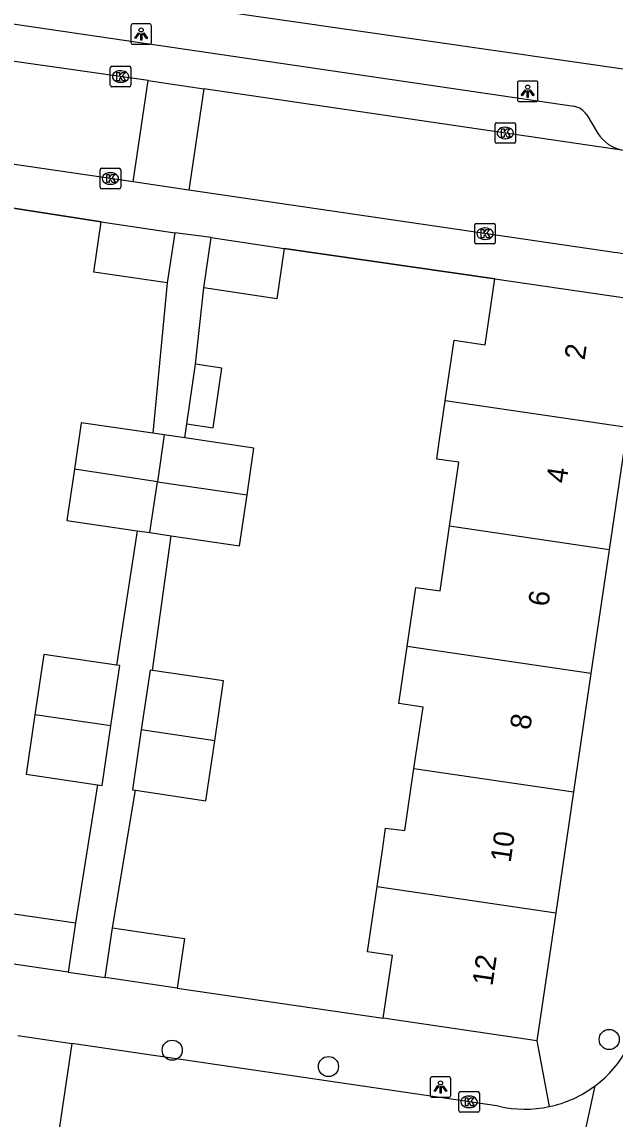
# Model space of a CAD drawing. Extents: x 163686 to 164493, y 382719 to 383870.
# Drawn here: x 163953.6 to 163982.4, y 383035.1 to 383088.5 of the extents above; entities that cross this region are included whole.
import ezdxf

# ---------------------------------------------------------------- set-up
doc = ezdxf.new("R2010")
doc.units = 0
for name, color, linetype in [('IMGEO_Boom', 7, 'Continuous'), ('IMGEO_Kolk', 7, 'Continuous'), ('IMGEO_Lichtpunt', 7, 'Continuous'), ('IMGEO_Muur', 7, 'Continuous'), ('IMGEO_Pand', 7, 'Continuous'), ('IMGEO_Pand_nummerreeks', 7, 'Continuous'), ('IMGEO_Rijbaan_lokaal_open', 7, 'Continuous'), ('IMGEO_Voetpad_open', 7, 'Continuous')]:
    doc.layers.add(name, color=color, linetype=linetype)

msp = doc.modelspace()

# ---------------------------------------------------------------- linework, layer by layer
at = {"layer": 'IMGEO_Boom'}
for centre in [(163982.12, 383039.005), (163960.885, 383038.485), (163968.477, 383037.689)]:
    msp.add_circle(centre, 0.489, dxfattribs=at)
at = {"layer": 'IMGEO_Kolk'}
for p, q in [((163957.877, 383085.406), (163957.877, 383086.258)), ((163957.952, 383086.332), (163958.804, 383086.332)), ((163958.365, 383086.112), (163958.39, 383086.112)), ((163958.878, 383086.258), (163958.878, 383085.406)), ((163958.804, 383085.332), (163957.952, 383085.332)), ((163958.388, 383085.552), (163958.363, 383085.552)), ((163976.57, 383082.663), (163976.57, 383083.515)), ((163976.645, 383083.589), (163977.497, 383083.589)), ((163977.571, 383083.515), (163977.571, 383082.663)), ((163977.058, 383083.369), (163977.083, 383083.369)), ((163977.497, 383082.589), (163976.645, 383082.589)), ((163977.081, 383082.809), (163977.056, 383082.809)), ((163957.454, 383081.373), (163958.306, 383081.373)), ((163957.379, 383080.447), (163957.379, 383081.299)), ((163957.867, 383081.153), (163957.892, 383081.153)), ((163958.38, 383081.299), (163958.38, 383080.447)), ((163958.306, 383080.373), (163957.454, 383080.373)), ((163957.89, 383080.593), (163957.865, 383080.593)), ((163975.659, 383078.691), (163976.511, 383078.691)), ((163975.584, 383077.765), (163975.584, 383078.617)), ((163976.072, 383078.471), (163976.097, 383078.471)), ((163976.585, 383078.617), (163976.585, 383077.765)), ((163976.511, 383077.691), (163975.659, 383077.691)), ((163976.095, 383077.911), (163976.07, 383077.911)), ((163974.812, 383035.548), (163974.812, 383036.4)), ((163974.887, 383036.474), (163975.739, 383036.474)), ((163975.3, 383036.254), (163975.325, 383036.254)), ((163975.813, 383036.4), (163975.813, 383035.548)), ((163975.739, 383035.474), (163974.887, 383035.474)), ((163975.323, 383035.694), (163975.298, 383035.694))]:
    msp.add_line(p, q, dxfattribs=at)
for points in [[(163957.877, 383085.406), (163957.877, 383086.258)], [(163957.952, 383086.332), (163958.804, 383086.332)], [(163958.878, 383086.258), (163958.878, 383085.406)], [(163958.198, 383086.032), (163958.321, 383086.032), (163958.321, 383085.881), (163958.451, 383086.032), (163958.615, 383086.032), (163958.469, 383085.881), (163958.622, 383085.632), (163958.47, 383085.632), (163958.385, 383085.796), (163958.321, 383085.729), (163958.321, 383085.632), (163958.198, 383085.632), (163958.198, 383086.032)], [(163958.804, 383085.332), (163957.952, 383085.332)], [(163976.57, 383082.663), (163976.57, 383083.515)], [(163976.645, 383083.589), (163977.497, 383083.589)], [(163977.571, 383083.515), (163977.571, 383082.663)], [(163976.891, 383083.289), (163977.014, 383083.289), (163977.014, 383083.138), (163977.144, 383083.289), (163977.308, 383083.289), (163977.162, 383083.138), (163977.315, 383082.889), (163977.163, 383082.889), (163977.078, 383083.053), (163977.014, 383082.986), (163977.014, 383082.889), (163976.891, 383082.889), (163976.891, 383083.289)], [(163977.497, 383082.589), (163976.645, 383082.589)], [(163957.454, 383081.373), (163958.306, 383081.373)], [(163957.379, 383080.447), (163957.379, 383081.299)], [(163957.7, 383081.073), (163957.823, 383081.073), (163957.823, 383080.922), (163957.953, 383081.073), (163958.117, 383081.073), (163957.971, 383080.922), (163958.124, 383080.673), (163957.972, 383080.673), (163957.887, 383080.837), (163957.823, 383080.77), (163957.823, 383080.673), (163957.7, 383080.673), (163957.7, 383081.073)], [(163958.38, 383081.299), (163958.38, 383080.447)], [(163958.306, 383080.373), (163957.454, 383080.373)], [(163975.659, 383078.691), (163976.511, 383078.691)], [(163975.584, 383077.765), (163975.584, 383078.617)], [(163975.905, 383078.391), (163976.028, 383078.391), (163976.028, 383078.24), (163976.158, 383078.391), (163976.322, 383078.391), (163976.176, 383078.24), (163976.329, 383077.991), (163976.177, 383077.991), (163976.092, 383078.155), (163976.028, 383078.088), (163976.028, 383077.991), (163975.905, 383077.991), (163975.905, 383078.391)], [(163976.585, 383078.617), (163976.585, 383077.765)], [(163976.511, 383077.691), (163975.659, 383077.691)], [(163974.812, 383035.548), (163974.812, 383036.4)], [(163974.887, 383036.474), (163975.739, 383036.474)], [(163975.133, 383036.174), (163975.256, 383036.174), (163975.256, 383036.023), (163975.386, 383036.174), (163975.55, 383036.174), (163975.404, 383036.023), (163975.557, 383035.774), (163975.405, 383035.774), (163975.32, 383035.938), (163975.256, 383035.871), (163975.256, 383035.774), (163975.133, 383035.774), (163975.133, 383036.174)], [(163975.813, 383036.4), (163975.813, 383035.548)], [(163975.739, 383035.474), (163974.887, 383035.474)]]:
    msp.add_lwpolyline(points, dxfattribs=at)
for centre, start, end in [((163957.954, 383086.256), 91.552, 178.448), ((163957.954, 383086.256), 91.552, 178.448), ((163958.802, 383086.256), 1.552, 88.448), ((163958.802, 383086.256), 1.552, 88.448), ((163957.954, 383085.408), 181.552, 268.448), ((163957.954, 383085.408), 181.552, 268.448), ((163958.802, 383085.408), 271.552, 358.448), ((163958.802, 383085.408), 271.552, 358.448), ((163976.647, 383083.513), 91.552, 178.448), ((163976.647, 383083.513), 91.552, 178.448), ((163977.495, 383083.513), 1.552, 88.448), ((163977.495, 383083.513), 1.552, 88.448), ((163976.647, 383082.665), 181.552, 268.448), ((163976.647, 383082.665), 181.552, 268.448), ((163977.495, 383082.665), 271.552, 358.448), ((163977.495, 383082.665), 271.552, 358.448), ((163957.456, 383081.297), 91.552, 178.448), ((163957.456, 383081.297), 91.552, 178.448), ((163958.304, 383081.297), 1.552, 88.448), ((163958.304, 383081.297), 1.552, 88.448), ((163957.456, 383080.449), 181.552, 268.448), ((163957.456, 383080.449), 181.552, 268.448), ((163958.304, 383080.449), 271.552, 358.448), ((163958.304, 383080.449), 271.552, 358.448), ((163975.661, 383078.615), 91.552, 178.448), ((163975.661, 383078.615), 91.552, 178.448), ((163976.509, 383078.615), 1.552, 88.448), ((163976.509, 383078.615), 1.552, 88.448), ((163975.661, 383077.767), 181.552, 268.448), ((163975.661, 383077.767), 181.552, 268.448), ((163976.509, 383077.767), 271.552, 358.448), ((163976.509, 383077.767), 271.552, 358.448), ((163974.889, 383036.398), 91.552, 178.448), ((163974.889, 383036.398), 91.552, 178.448), ((163975.737, 383036.398), 1.552, 88.448), ((163975.737, 383036.398), 1.552, 88.448), ((163974.889, 383035.55), 181.552, 268.448), ((163974.889, 383035.55), 181.552, 268.448), ((163975.737, 383035.55), 271.552, 358.448), ((163975.737, 383035.55), 271.552, 358.448)]:
    msp.add_arc(centre, 0.0765, start, end, dxfattribs=at)
for centre, major_axis, ratio, start_param, end_param in [((163958.364, 383085.832), (-0.387, 0.002), 0.722429, 4.712389, 7.853982), ((163958.389, 383085.832), (-0.39, 0.002), 0.717154, 1.570796, 4.712389), ((163977.057, 383083.089), (-0.387, 0.002), 0.722429, 4.712389, 7.853982), ((163977.082, 383083.089), (-0.39, 0.002), 0.717154, 1.570796, 4.712389), ((163957.866, 383080.873), (-0.387, 0.002), 0.722429, 4.712389, 7.853982), ((163957.891, 383080.873), (-0.39, 0.002), 0.717154, 1.570796, 4.712389), ((163976.071, 383078.191), (-0.387, 0.002), 0.722429, 4.712389, 7.853982), ((163976.096, 383078.191), (-0.39, 0.002), 0.717154, 1.570796, 4.712389), ((163975.299, 383035.974), (-0.387, 0.002), 0.722429, 4.712389, 7.853982), ((163975.324, 383035.974), (-0.39, 0.002), 0.717154, 1.570796, 4.712389)]:
    msp.add_ellipse(centre, major_axis=major_axis, ratio=ratio, start_param=start_param, end_param=end_param, dxfattribs=at)
at = {"layer": 'IMGEO_Lichtpunt'}
for p, q in [((163958.878, 383088.301), (163958.878, 383087.494)), ((163958.878, 383088.301), (163958.878, 383087.494)), ((163959.78, 383088.396), (163958.972, 383088.396)), ((163959.78, 383088.396), (163958.972, 383088.396)), ((163959.874, 383087.494), (163959.874, 383088.301)), ((163959.874, 383087.494), (163959.874, 383088.301)), ((163958.972, 383087.4), (163959.78, 383087.4)), ((163958.972, 383087.4), (163959.78, 383087.4)), ((163978.561, 383085.615), (163977.753, 383085.615)), ((163978.561, 383085.615), (163977.753, 383085.615)), ((163977.659, 383085.52), (163977.659, 383084.713)), ((163977.659, 383085.52), (163977.659, 383084.713)), ((163978.655, 383084.713), (163978.655, 383085.52)), ((163978.655, 383084.713), (163978.655, 383085.52)), ((163977.753, 383084.619), (163978.561, 383084.619)), ((163977.753, 383084.619), (163978.561, 383084.619)), ((163973.424, 383037.097), (163973.424, 383036.29)), ((163973.424, 383037.097), (163973.424, 383036.29)), ((163974.326, 383037.192), (163973.518, 383037.192)), ((163974.326, 383037.192), (163973.518, 383037.192)), ((163974.42, 383036.29), (163974.42, 383037.097)), ((163974.42, 383036.29), (163974.42, 383037.097)), ((163973.518, 383036.196), (163974.326, 383036.196)), ((163973.518, 383036.196), (163974.326, 383036.196))]:
    msp.add_line(p, q, dxfattribs=at)
for points in [[(163959.252, 383087.965), (163959.291, 383087.937), (163959.103, 383087.675), (163959.065, 383087.702), (163959.252, 383087.965)], [(163959.354, 383087.917), (163959.401, 383087.917), (163959.401, 383087.595), (163959.354, 383087.595), (163959.354, 383087.917)], [(163959.464, 383087.937), (163959.502, 383087.964), (163959.689, 383087.702), (163959.65, 383087.674), (163959.464, 383087.937)], [(163978.033, 383085.184), (163978.072, 383085.156), (163977.884, 383084.894), (163977.846, 383084.921), (163978.033, 383085.184)], [(163978.135, 383085.136), (163978.182, 383085.136), (163978.182, 383084.814), (163978.135, 383084.814), (163978.135, 383085.136)], [(163978.245, 383085.156), (163978.283, 383085.183), (163978.47, 383084.921), (163978.431, 383084.893), (163978.245, 383085.156)], [(163973.798, 383036.761), (163973.837, 383036.733), (163973.649, 383036.471), (163973.611, 383036.498), (163973.798, 383036.761)], [(163973.9, 383036.713), (163973.947, 383036.713), (163973.947, 383036.391), (163973.9, 383036.391), (163973.9, 383036.713)], [(163974.01, 383036.733), (163974.048, 383036.76), (163974.235, 383036.498), (163974.196, 383036.47), (163974.01, 383036.733)]]:
    msp.add_lwpolyline(points, dxfattribs=at)
for centre in [(163959.377, 383088.099), (163978.158, 383085.318), (163973.923, 383036.895)]:
    msp.add_circle(centre, 0.0994, dxfattribs=at)
for centre, start, end in [((163958.972, 383088.301), 90, 180), ((163958.972, 383088.301), 90, 180), ((163959.78, 383088.301), 0, 90), ((163959.78, 383088.301), 0, 90), ((163958.972, 383087.494), 180, 270), ((163958.972, 383087.494), 180, 270), ((163959.78, 383087.494), 270, 0), ((163959.78, 383087.494), 270, 360), ((163977.753, 383085.52), 90, 180), ((163977.753, 383085.52), 90, 180), ((163978.561, 383085.52), 0, 90), ((163978.561, 383085.52), 0, 90), ((163977.753, 383084.713), 180, 270), ((163977.753, 383084.713), 180, 270), ((163978.561, 383084.713), 270, 0), ((163978.561, 383084.713), 270, 360), ((163973.518, 383037.097), 90, 180), ((163973.518, 383037.097), 90, 180), ((163974.326, 383037.097), 0, 90), ((163974.326, 383037.097), 0, 90), ((163973.518, 383036.29), 180, 270), ((163973.518, 383036.29), 180, 270), ((163974.326, 383036.29), 270, 0), ((163974.326, 383036.29), 270, 360)]:
    msp.add_arc(centre, 0.0946, start, end, dxfattribs=at)
at = {"layer": 'IMGEO_Muur'}
for points in [[(163948.468, 383080.158), (163957.439, 383078.766)], [(163966.326, 383077.478), (163976.556, 383076.003)], [(163961.128, 383041.5), (163971.14, 383040.041)]]:
    msp.add_lwpolyline(points, dxfattribs=at)
at = {"layer": 'IMGEO_Pand'}
for points in [[(163960.646, 383075.798), (163957.079, 383076.324), (163957.439, 383078.766)], [(163957.439, 383078.766), (163961.006, 383078.24)], [(163961.006, 383078.24), (163960.646, 383075.798)], [(163962.416, 383075.55), (163962.777, 383078.001)], [(163962.777, 383078.001), (163966.326, 383077.478)], [(163966.326, 383077.478), (163965.965, 383075.027), (163962.416, 383075.55)], [(163974.15, 383070.061), (163974.585, 383073.015), (163976.084, 383072.794), (163976.556, 383076.003)], [(163976.556, 383076.003), (163983.897, 383074.923)], [(163961.588, 383068.937), (163962.016, 383071.842)], [(163961.588, 383068.937), (163962.87, 383068.749), (163963.297, 383071.653), (163962.016, 383071.842)], [(163974.361, 383063.962), (163974.819, 383067.073), (163973.749, 383067.229), (163973.857, 383068.069), (163974.15, 383070.061)], [(163982.99, 383068.76), (163974.15, 383070.061)], [(163959.944, 383068.49), (163956.466, 383069.001), (163956.133, 383066.738)], [(163982.99, 383068.76), (163982.116, 383062.821)], [(163960.492, 383068.409), (163959.944, 383068.49)], [(163960.492, 383068.409), (163960.166, 383066.125)], [(163961.493, 383068.261), (163960.492, 383068.409)], [(163964.522, 383065.496), (163964.856, 383067.766), (163961.493, 383068.261)], [(163956.133, 383066.738), (163955.766, 383064.246), (163959.178, 383063.743)], [(163960.166, 383066.125), (163956.133, 383066.738)], [(163959.792, 383063.653), (163960.166, 383066.125)], [(163960.166, 383066.125), (163964.522, 383065.496)], [(163960.834, 383063.5), (163964.156, 383063.011), (163964.522, 383065.496)], [(163959.178, 383063.743), (163959.792, 383063.653)], [(163972.299, 383058.122), (163972.721, 383060.989), (163973.898, 383060.816), (163974.361, 383063.962)], [(163982.116, 383062.821), (163974.361, 383063.962)], [(163959.792, 383063.653), (163960.834, 383063.5)], [(163982.116, 383062.821), (163981.231, 383056.809)], [(163972.632, 383052.182), (163973.072, 383055.163), (163971.89, 383055.338), (163972.299, 383058.122)], [(163981.231, 383056.809), (163972.299, 383058.122)], [(163958.178, 383057.208), (163954.643, 383057.729), (163954.211, 383054.796)], [(163957.905, 383054.252), (163958.337, 383057.185), (163958.178, 383057.208)], [(163959.926, 383056.951), (163959.81, 383056.968), (163959.381, 383054.057)], [(163962.951, 383053.531), (163963.38, 383056.443), (163959.926, 383056.951)], [(163981.231, 383056.809), (163980.383, 383051.042)], [(163954.211, 383054.796), (163953.785, 383051.905), (163957.257, 383051.394)], [(163957.905, 383054.252), (163954.211, 383054.796)], [(163957.257, 383051.394), (163957.479, 383051.361), (163957.905, 383054.252)], [(163959.381, 383054.057), (163958.952, 383051.145), (163959.1, 383051.123)], [(163962.951, 383053.531), (163959.381, 383054.057)], [(163959.1, 383051.123), (163962.522, 383050.619), (163962.951, 383053.531)], [(163970.837, 383046.45), (163971.097, 383048.215), (163971.254, 383049.285), (163972.186, 383049.166), (163972.632, 383052.182)], [(163972.632, 383052.182), (163980.383, 383051.042)], [(163980.383, 383051.042), (163979.519, 383045.173)], [(163971.14, 383040.041), (163971.59, 383043.094), (163970.37, 383043.274), (163970.837, 383046.45)], [(163970.837, 383046.45), (163979.519, 383045.173)], [(163952.285, 383042.801), (163952.639, 383045.203), (163956.182, 383044.681)], [(163979.519, 383045.173), (163978.602, 383038.943)], [(163956.182, 383044.681), (163955.828, 383042.279)], [(163957.633, 383042.015), (163957.989, 383044.433)], [(163957.989, 383044.433), (163961.484, 383043.918), (163961.128, 383041.5)], [(163955.828, 383042.279), (163952.285, 383042.801)], [(163961.128, 383041.5), (163957.633, 383042.015)], [(163978.602, 383038.943), (163971.14, 383040.041)]]:
    msp.add_lwpolyline(points, dxfattribs=at)
at = {"layer": 'IMGEO_Rijbaan_lokaal_open'}
for points in [[(163959.722, 383085.634), (163932.249, 383089.563)], [(163958.995, 383080.707), (163959.722, 383085.634)], [(163959.722, 383085.634), (163962.422, 383085.238)], [(163962.422, 383085.238), (163961.696, 383080.313)], [(163982.824, 383082.244), (163962.422, 383085.238)], [(163958.995, 383080.707), (163940.003, 383083.479)], [(163961.696, 383080.313), (163958.995, 383080.707)], [(163982.353, 383077.269), (163961.696, 383080.313)], [(163953.381, 383039.199), (163956.003, 383038.814)], [(163956.003, 383038.814), (163955.204, 383033.334)], [(163976.752, 383035.761), (163956.003, 383038.814)], [(163979.634, 383028.448), (163981.438, 383036.755)]]:
    msp.add_lwpolyline(points, dxfattribs=at)
for centre, radius, start, end in [((163982.192, 383074.03), 3.243, 37.739, 87.1456), ((163978.026, 383041.299), 5.682, 306.9034, 356.756), ((163978.019, 383041.312), 5.697, 282.0123, 306.8756), ((163978.026, 383041.318), 5.701, 257.0853, 281.9337)]:
    msp.add_arc(centre, radius, start, end, dxfattribs=at)
at = {"layer": 'IMGEO_Voetpad_open'}
for points in [[(163983.586, 383086.072), (163934.941, 383093.086), (163933.019, 383093.411), (163931.289, 383095.487)], [(163935.35, 383091.023), (163980.406, 383084.391)], [(163981.034, 383083.974), (163981.545, 383083.101)], [(163957.439, 383078.766), (163948.468, 383080.158)], [(163962.777, 383078.001), (163961.006, 383078.24)], [(163976.556, 383076.003), (163966.326, 383077.478)], [(163960.646, 383075.798), (163959.944, 383068.49)], [(163962.016, 383071.842), (163962.416, 383075.55)], [(163961.493, 383068.261), (163961.588, 383068.937)], [(163959.178, 383063.743), (163958.178, 383057.208)], [(163959.926, 383056.951), (163960.834, 383063.5)], [(163957.257, 383051.394), (163956.182, 383044.681)], [(163957.989, 383044.433), (163959.1, 383051.123)], [(163955.828, 383042.279), (163957.633, 383042.015)], [(163961.128, 383041.5), (163971.14, 383040.041)], [(163978.602, 383038.943), (163979.205, 383035.74)]]:
    msp.add_lwpolyline(points, dxfattribs=at)
for centre, radius, start, end in [((163980.157, 383083.334), 1.086, 36.0986, 76.7321), ((163983.111, 383084.056), 1.834, 211.3651, 260.9864)]:
    msp.add_arc(centre, radius, start, end, dxfattribs=at)

# ---------------------------------------------------------------- texts
at = {"layer": 'IMGEO_Pand_nummerreeks'}
for s, rotation, p in [('2', 81.6281, (163980.923, 383072.017)), ('4', 81.6281, (163980.04, 383066.022)), ('6', 81.6281, (163979.158, 383060.026)), ('8', 81.6281, (163978.276, 383054.033)), ('10', 81.6281, (163977.327, 383047.58)), ('12', 81.6282, (163976.443, 383041.578))]:
    msp.add_text(s, height=1, rotation=rotation, dxfattribs=at).set_placement(p)

doc.saveas('drawing.dxf')
